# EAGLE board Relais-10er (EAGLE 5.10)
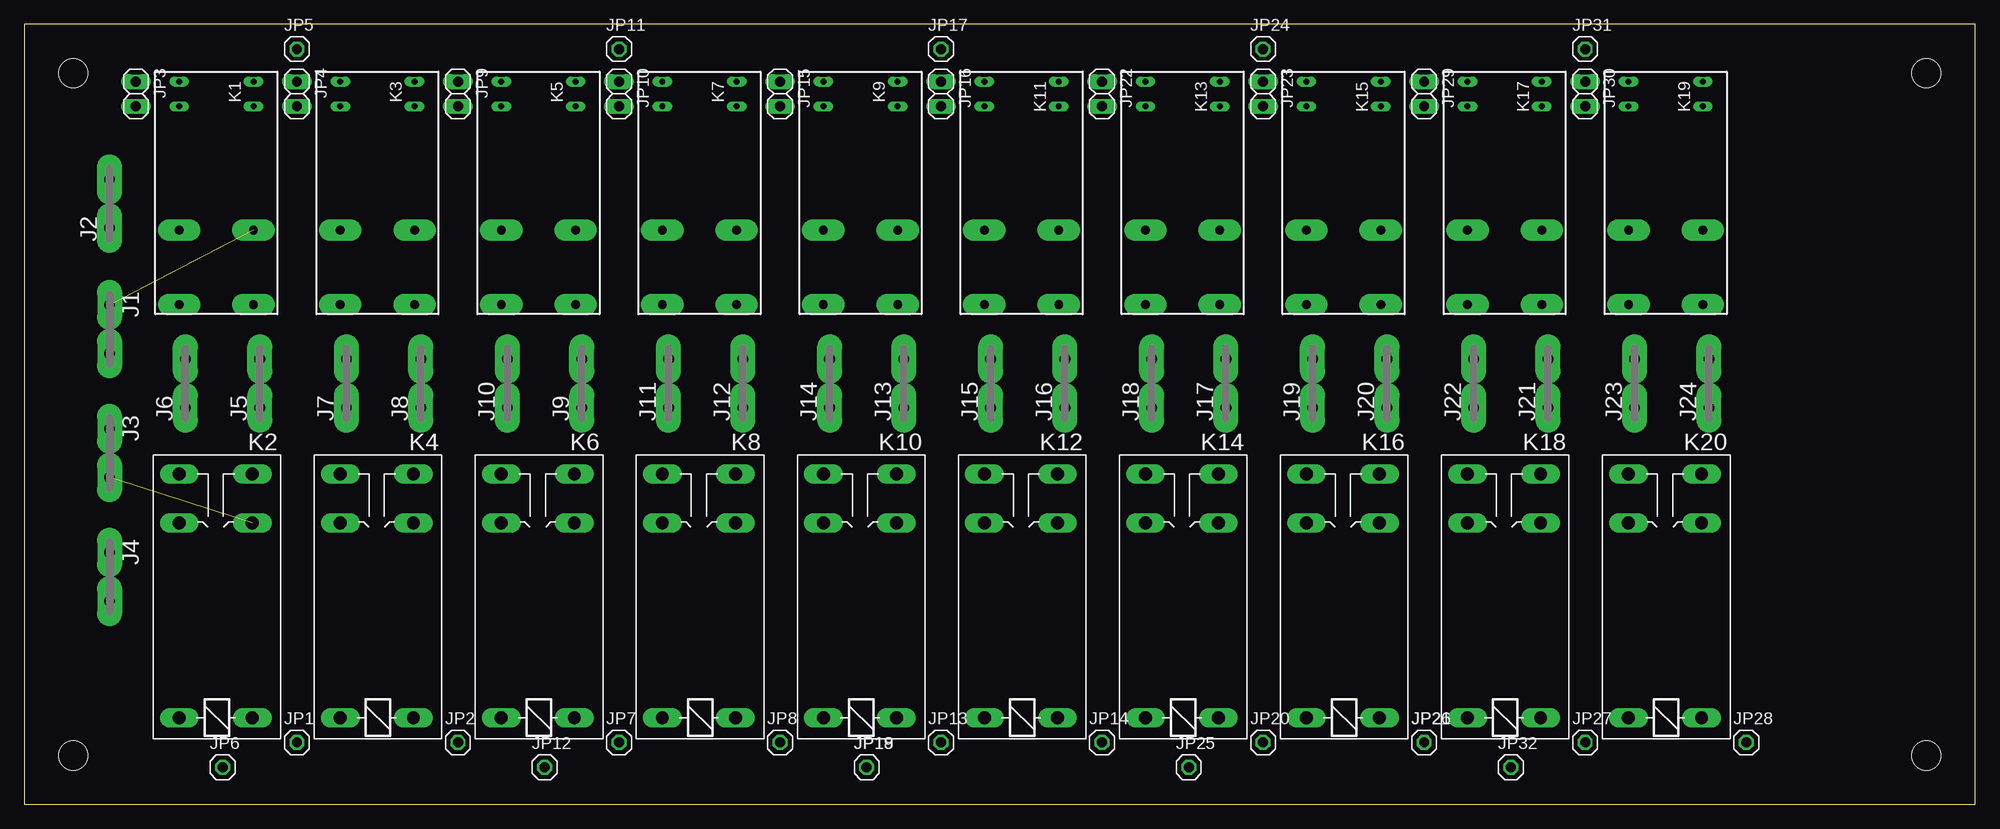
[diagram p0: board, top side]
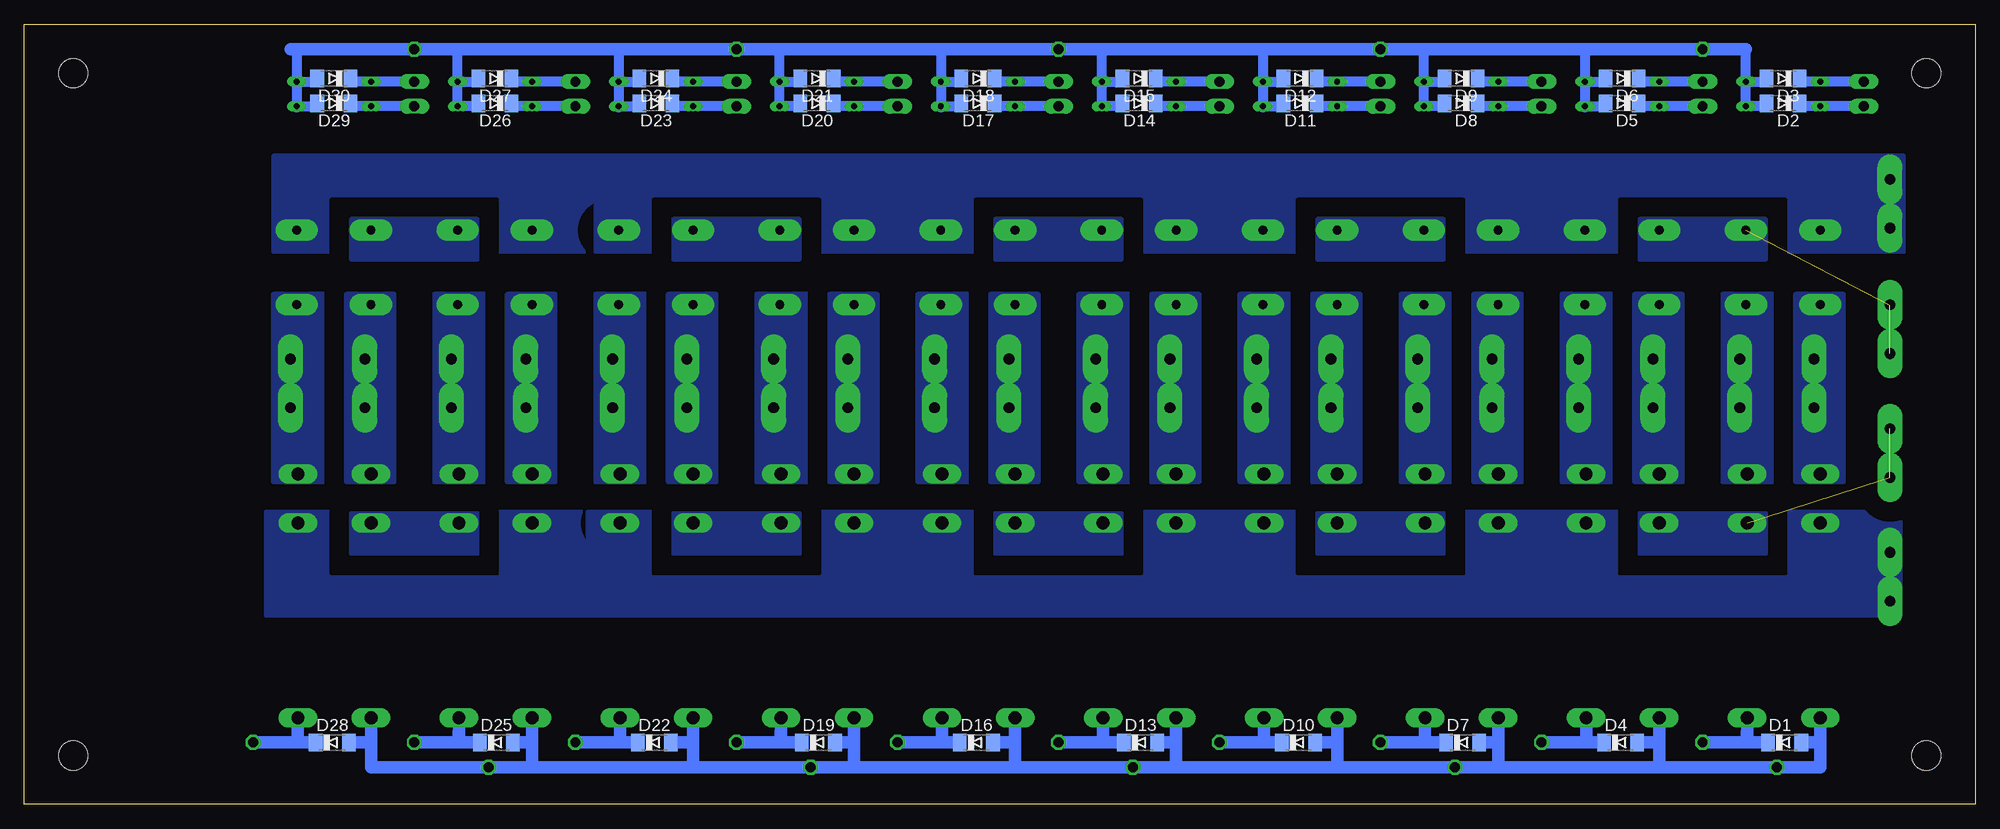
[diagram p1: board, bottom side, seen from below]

Size 200 x 80 mm. Coordinates in mm from the lower left corner, seen from the top.
Outline: 0,0 200,0 200,80 0,80 0,0
Copper layers (1+2*15+16): Top 0.035mm / dielectric 0.36mm / layer 2 0.018mm / dielectric 0.71mm / layer 15 0.018mm / dielectric 0.36mm / Bottom 0.035mm
Design rules "q-print.info": minimum track width 6mil, minimum drill 0.3mm, track to track 6mil, track to pad 6mil, pad to pad 6mil, via to via 6mil, smd to smd 6mil, copper to edge 8mil, drill to drill 10mil, minimum pad ring 8mil, minimum via ring 8mil, stop-mask expansion 4mil, vias tented up to drill 16mil, thermal gap 10mil
Net classes: 1 mains: width 4 mm, clearance 2 mm
Holes 3 mm at 5,75 5,5 195,5 195,75

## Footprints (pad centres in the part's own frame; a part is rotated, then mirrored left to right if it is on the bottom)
MINIMELF = smd 1.4 x 1.8: A 1.7,0; C -1.7,0
F061.080 = drill 1.1 pad 2.54 long: 1A -2.5,0; 1B 2.5,0
1X01 = drill 1.016 octagon: 1 0,0
1X02 = drill 1.016 long: 1 -1.27,0; 2 1.27,0
DE2A-L2 = drill 0.61 long: 1 -8.89,-3.81; 2 -6.35,-3.81; 7 -6.35,3.81; 8 -8.89,3.81 | drill 0.9 pad 2.184 long: 3 6.35,-3.81; 4 13.97,-3.81; 5 13.97,3.81; 6 6.35,3.81
G2R2A = drill 1.321 long: 1 -2.54,-3.683; 2 -2.54,3.81; P1 17.45,3.81; P2 17.45,-3.683; S1 22.454,3.81; S2 22.454,-3.683

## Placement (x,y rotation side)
D1  1N4148DO35-7  [MINIMELF]  19.53,6.35 0 bottom
D2  1N4148DO35-7  [MINIMELF]  19.68,71.91 180 bottom
D3  1N4148DO35-7  [MINIMELF]  19.68,74.45 180 bottom
D4  1N4148DO35-7  [MINIMELF]  36.35,6.35 0 bottom
D5  1N4148DO35-7  [MINIMELF]  36.19,71.91 180 bottom
D6  1N4148DO35-7  [MINIMELF]  36.2,74.45 180 bottom
D7  1N4148DO35-7  [MINIMELF]  52.55,6.35 0 bottom
D8  1N4148DO35-7  [MINIMELF]  52.7,71.91 180 bottom
D9  1N4148DO35-7  [MINIMELF]  52.7,74.45 180 bottom
D10  1N4148DO35-7  [MINIMELF]  69.37,6.35 0 bottom
D11  1N4148DO35-7  [MINIMELF]  69.21,71.91 180 bottom
D12  1N4148DO35-7  [MINIMELF]  69.22,74.45 180 bottom
D13  1N4148DO35-7  [MINIMELF]  85.57,6.35 0 bottom
D14  1N4148DO35-7  [MINIMELF]  85.72,71.91 180 bottom
D15  1N4148DO35-7  [MINIMELF]  85.72,74.45 180 bottom
D16  1N4148DO35-7  [MINIMELF]  102.39,6.35 0 bottom
D17  1N4148DO35-7  [MINIMELF]  102.23,71.91 180 bottom
D18  1N4148DO35-7  [MINIMELF]  102.23,74.45 180 bottom
D19  1N4148DO35-7  [MINIMELF]  118.59,6.35 0 bottom
D20  1N4148DO35-7  [MINIMELF]  118.75,71.91 180 bottom
D21  1N4148DO35-7  [MINIMELF]  118.74,74.45 180 bottom
D22  1N4148DO35-7  [MINIMELF]  135.41,6.35 0 bottom
D23  1N4148DO35-7  [MINIMELF]  135.25,71.91 180 bottom
D24  1N4148DO35-7  [MINIMELF]  135.25,74.45 180 bottom
D25  1N4148DO35-7  [MINIMELF]  151.61,6.35 0 bottom
D26  1N4148DO35-7  [MINIMELF]  151.76,71.91 180 bottom
D27  1N4148DO35-7  [MINIMELF]  151.76,74.45 180 bottom
D28  1N4148DO35-7  [MINIMELF]  168.43,6.35 0 bottom
D29  1N4148DO35-7  [MINIMELF]  168.27,71.91 180 bottom
D30  1N4148DO35-7  [MINIMELF]  168.28,74.45 180 bottom
J1  Netz-X1  [F061.080]  8.73,48.74 270 top
J2  Netz-X2  [F061.080]  8.73,61.59 90 top
J3  Schalter-X1  [F061.080]  8.73,36.04 270 top
J4  Schalter-X2  [F061.080]  8.73,23.34 270 top
J5  A1-X1  [F061.080]  24.13,43.18 90 top
J6  A1-X2  [F061.080]  16.51,43.18 90 top
J7  A2-X1  [F061.080]  33.02,43.18 90 top
J8  A2-X2  [F061.080]  40.64,43.18 90 top
J9  A1-X1  [F061.080]  57.15,43.18 90 top
J10  A1-X2  [F061.080]  49.53,43.18 90 top
J11  A2-X1  [F061.080]  66.04,43.18 90 top
J12  A2-X2  [F061.080]  73.66,43.18 90 top
J13  A1-X1  [F061.080]  90.17,43.18 90 top
J14  A1-X2  [F061.080]  82.55,43.18 90 top
J15  A2-X1  [F061.080]  99.06,43.18 90 top
J16  A2-X2  [F061.080]  106.68,43.18 90 top
J17  A1-X1  [F061.080]  123.19,43.18 90 top
J18  A1-X2  [F061.080]  115.57,43.18 90 top
J19  A2-X1  [F061.080]  132.08,43.18 90 top
J20  A2-X2  [F061.080]  139.7,43.18 90 top
J21  A1-X1  [F061.080]  156.21,43.18 90 top
J22  A1-X2  [F061.080]  148.59,43.18 90 top
J23  A2-X1  [F061.080]  165.1,43.18 90 top
J24  A2-X2  [F061.080]  172.72,43.18 90 top
JP1  [1X01]  27.94,6.35 0 top
JP2  [1X01]  44.45,6.35 0 top
JP3  [1X02]  11.43,72.87 270 top
JP4  [1X02]  27.94,72.87 270 top
JP5  [1X01]  27.94,77.47 0 top
JP6  [1X01]  20.32,3.81 0 top
JP7  [1X01]  60.96,6.35 0 top
JP8  [1X01]  77.47,6.35 0 top
JP9  [1X02]  44.45,72.87 270 top
JP10  [1X02]  60.96,72.87 270 top
JP11  [1X01]  60.96,77.47 0 top
JP12  [1X01]  53.34,3.81 0 top
JP13  [1X01]  93.98,6.35 0 top
JP14  [1X01]  110.49,6.35 0 top
JP15  [1X02]  77.47,72.87 270 top
JP16  [1X02]  93.98,72.87 270 top
JP17  [1X01]  93.98,77.47 0 top
JP18  [1X01]  86.36,3.81 0 top
JP19  [1X01]  86.36,3.81 0 top
JP20  [1X01]  127,6.35 0 top
JP21  [1X01]  143.51,6.35 0 top
JP22  [1X02]  110.49,72.87 270 top
JP23  [1X02]  127,72.87 270 top
JP24  [1X01]  127,77.47 0 top
JP25  [1X01]  119.38,3.81 0 top
JP26  [1X01]  143.51,6.35 0 top
JP27  [1X01]  160.02,6.35 0 top
JP28  [1X01]  176.53,6.35 0 top
JP29  [1X02]  143.51,72.87 270 top
JP30  [1X02]  160.02,72.87 270 top
JP31  [1X01]  160.02,77.47 0 top
JP32  [1X01]  152.4,3.81 0 top
K1  DE2A-L2  [DE2A-L2]  19.68,65.25 270 top
K2  G2R2A  [G2R2A]  19.68,11.43 90 top
K3  DE2A-L2  [DE2A-L2]  36.2,65.25 270 top
K4  G2R2A  [G2R2A]  36.2,11.43 90 top
K5  DE2A-L2  [DE2A-L2]  52.7,65.25 270 top
K6  G2R2A  [G2R2A]  52.7,11.43 90 top
K7  DE2A-L2  [DE2A-L2]  69.22,65.25 270 top
K8  G2R2A  [G2R2A]  69.22,11.43 90 top
K9  DE2A-L2  [DE2A-L2]  85.72,65.25 270 top
K10  G2R2A  [G2R2A]  85.72,11.43 90 top
K11  DE2A-L2  [DE2A-L2]  102.23,65.25 270 top
K12  G2R2A  [G2R2A]  102.23,11.43 90 top
K13  DE2A-L2  [DE2A-L2]  118.75,65.25 270 top
K14  G2R2A  [G2R2A]  118.75,11.43 90 top
K15  DE2A-L2  [DE2A-L2]  135.25,65.25 270 top
K16  G2R2A  [G2R2A]  135.25,11.43 90 top
K17  DE2A-L2  [DE2A-L2]  151.76,65.25 270 top
K18  G2R2A  [G2R2A]  151.76,11.43 90 top
K19  DE2A-L2  [DE2A-L2]  168.28,65.25 270 top
K20  G2R2A  [G2R2A]  168.28,11.43 90 top

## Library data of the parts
D1-D30 = diode
J1-J24 = con-faston
JP1-JP32 = pinhead
K1 K3 K5 K7 K9 K11 K13 K15 K17 K19 = 11my-mechanics
K2 K4 K6 K8 K10 K12 K14 K16 K18 K20 = relay

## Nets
N$1 [mains]: J1.1A J1.1B K1.6 K3.3
N$2 [mains]: J2.1A J2.1B K1.3 K3.6
N$3 [mains]: J5.1A J5.1B K1.5 K2.S2
N$4 [mains]: J6.1A J6.1B K1.4 K2.S1
N$5 [mains]: J4.1A J4.1B K2.P1 K4.P2
N$6 [mains]: J3.1A J3.1B K2.P2 K4.P1
N$7: D2.A D3.A D5.A D6.A JP5.1 K1.7 K1.8 K3.7 K3.8
N$8: D3.C JP3.1 K1.1
N$9: D2.C JP3.2 K1.2
N$10 [mains]: K5.6 K7.3
N$11: D1.C JP1.1 K2.1
N$12 [mains]: K5.3 K7.6
N$13: D1.A D4.A JP6.1 K2.2 K4.2
N$14 [mains]: J7.1A J7.1B K3.4 K4.S1
N$15 [mains]: J8.1A J8.1B K3.5 K4.S2
N$16 [mains]: J9.1A J9.1B K5.5 K6.S2
N$17 [mains]: J10.1A J10.1B K5.4 K6.S1
N$18 [mains]: K6.P1 K8.P2
N$19: D6.C JP4.1 K3.1
N$20: D5.C JP4.2 K3.2
N$21 [mains]: K6.P2 K8.P1
N$22: D4.C JP2.1 K4.1
N$23: D8.A D9.A D11.A D12.A JP11.1 K5.7 K5.8 K7.7 K7.8
N$24: D9.C JP9.1 K5.1
N$25: D8.C JP9.2 K5.2
N$26: D7.C JP7.1 K6.1
N$27 [mains]: J11.1A J11.1B K7.4 K8.S1
N$28 [mains]: J12.1A J12.1B K7.5 K8.S2
N$29: D12.C JP10.1 K7.1
N$30: D11.C JP10.2 K7.2
N$31: D10.C JP8.1 K8.1
N$32: D7.A D10.A JP12.1 K6.2 K8.2
N$33 [mains]: K9.6 K11.3
N$35 [mains]: K9.3 K11.6
N$36 [mains]: J13.1A J13.1B K9.5 K10.S2
N$38 [mains]: J14.1A J14.1B K9.4 K10.S1
N$39 [mains]: K10.P1 K12.P2
N$40 [mains]: K10.P2 K12.P1
N$41: D14.A D15.A D17.A D18.A JP17.1 K9.7 K9.8 K11.7 K11.8
N$42: D15.C JP15.1 K9.1
N$43: D14.C JP15.2 K9.2
N$44: D13.C JP13.1 K10.1
N$45 [mains]: J15.1A J15.1B K11.4 K12.S1
N$46 [mains]: J16.1A J16.1B K11.5 K12.S2
N$47: D18.C JP16.1 K11.1
N$48: D17.C JP16.2 K11.2
N$49: D16.C JP14.1 K12.1
N$50: D13.A D16.A JP19.1 K10.2 K12.2
N$51 [mains]: K13.6 K15.3
N$52 [mains]: K13.3 K15.6
N$53 [mains]: J17.1A J17.1B K13.5 K14.S2
N$54 [mains]: J18.1A J18.1B K13.4 K14.S1
N$55 [mains]: K14.P1 K16.P2
N$56 [mains]: K14.P2 K16.P1
N$57: D20.A D21.A D23.A D24.A JP24.1 K13.7 K13.8 K15.7 K15.8
N$58: D21.C JP22.1 K13.1
N$59: D20.C JP22.2 K13.2
N$60: D19.C JP20.1 K14.1
N$61 [mains]: J19.1A J19.1B K15.4 K16.S1
N$62 [mains]: J20.1A J20.1B K15.5 K16.S2
N$63: D24.C JP23.1 K15.1
N$64: D23.C JP23.2 K15.2
N$65: D22.C JP21.1 K16.1
N$66: D19.A D22.A JP25.1 K14.2 K16.2
N$70: JP26.1
N$72 [mains]: K17.6 K19.3
N$73 [mains]: K17.3 K19.6
N$74 [mains]: J21.1A J21.1B K17.5 K18.S2
N$75 [mains]: J22.1A J22.1B K17.4 K18.S1
N$76 [mains]: K18.P1 K20.P2
N$77 [mains]: K18.P2 K20.P1
N$78: D26.A D27.A D29.A D30.A JP31.1 K17.7 K17.8 K19.7 K19.8
N$79: D27.C JP29.1 K17.1
N$80: D26.C JP29.2 K17.2
N$81: D25.C JP27.1 K18.1
N$82 [mains]: J23.1A J23.1B K19.4 K20.S1
N$83 [mains]: J24.1A J24.1B K19.5 K20.S2
N$84: D30.C JP30.1 K19.1
N$85: D29.C JP30.2 K19.2
N$86: D28.C K20.1
N$87: D25.A D28.A JP32.1 K18.2 K20.2

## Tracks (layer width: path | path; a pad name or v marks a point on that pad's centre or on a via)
N$1  (2 unrouted)
  pour Bottom (no thermals): 21.43,60.01 34.45,60.01 34.45,55.88 21.43,55.88
N$2
  pour Bottom (isolate 2, rank 3, no thermals): 53.82,66.52 53.82,56.67 7.3,56.67 7.3,66.52
N$3
  pour Bottom (isolate 2, rank 4, no thermals): 19.68,33.02 25.88,33.02 25.88,52.39 19.68,52.39
N$4
  pour Bottom (isolate 2, no thermals): 13.49,52.39 13.49,33.02 18.41,33.02 18.42,52.39
N$5
  pour Bottom (isolate 2, rank 2, no thermals): 7.62,19.37 7.62,30 53.34,30 53.34,19.37
N$6  (2 unrouted)
  pour Bottom (no thermals): 21.43,29.84 34.45,29.84 34.45,25.72 21.43,25.72
N$7
  Bottom 1.016: K1.8 21.39,74.14 D3.A | D2.A 21.39,71.6 K1.7 K1.8 | K3.8 37.9,74.14 D6.A | K1.8 23.5,77.47 | K3.8 K3.7 37.9,71.6 D5.A | K3.8 40.01,77.47 40.64,77.47
  Bottom 1.27: 23.5,77.47 JP5.1 40.64,77.47 59.69,77.47 | K3.7
N$8
  Bottom 1.016: D3.C 17.98,74.14 K1.1 JP3.1
N$9
  Bottom 1.016: D2.C 17.98,71.6 K1.2 JP3.2
N$10
  pour Bottom (no thermals): 54.45,60.01 67.47,60.01 67.47,55.88 54.45,55.88
N$11
  Bottom 1.27: JP1.1 23.4,6.35 23.37,8.92 K2.1 23.37,6.35 D1.C
N$12
  pour Bottom (isolate 2, rank 3, no thermals): 84.3,66.52 84.3,56.67 40.32,56.67 40.32,66.52
N$13
  Bottom 1.27: 32.38,3.81 JP6.1 15.88,3.81 K2.2 15.88,6.35 D1.A | 32.38,3.81 32.38,6.35 | 32.38,6.35 K4.2 | 32.38,3.81 53.34,3.81 | 32.38,6.35 D4.A
N$14
  pour Bottom (isolate 2, no thermals): 34.92,52.39 30,52.39 30,33.02 34.92,33.02
N$15
  pour Bottom (isolate 2, rank 4, no thermals): 36.2,33.02 42.39,33.02 42.39,52.39 36.2,52.39
N$16
  pour Bottom (isolate 2, rank 4, no thermals): 52.7,33.02 58.9,33.02 58.9,52.39 52.7,52.39
N$17
  pour Bottom (isolate 2, no thermals): 46.51,52.39 46.51,33.02 51.44,33.02 51.44,52.39
N$18
  pour Bottom (isolate 2, rank 2, no thermals): 40.64,19.37 40.64,30 85.09,30 85.09,19.37
N$19
  Bottom 1.016: D6.C 34.49,74.14 K3.1 JP4.1
N$20
  Bottom 1.016: D5.C 34.49,71.6 K3.2 JP4.2
N$21
  pour Bottom (no thermals): 54.45,29.84 67.47,29.84 67.47,25.72 54.45,25.72
N$22
  Bottom 1.27: D4.C 39.88,6.35 | 39.88,6.35 K4.1 | 39.88,6.35 JP2.1
N$23
  Bottom 1.016: K5.8 54.41,74.14 D9.A | D8.A 54.41,71.6 K5.7 K5.8 | K7.8 70.92,74.14 D12.A | K5.8 56.52,77.47 | K7.8 K7.7 70.92,71.6 D11.A | K7.8 73.03,77.47 73.66,77.47
  Bottom 1.27: 56.52,77.47 JP11.1 73.66,77.47 90.17,77.47 | K7.7
N$24
  Bottom 1.016: D9.C 51.01,74.14 K5.1 JP9.1
N$25
  Bottom 1.016: D8.C 51.01,71.6 K5.2 JP9.2
N$26
  Bottom 1.27: JP7.1 56.42,6.35 56.39,8.92 K6.1 56.39,6.35 D7.C
N$27
  pour Bottom (isolate 2, no thermals): 67.94,52.39 63.02,52.39 63.02,33.02 67.94,33.02
N$28
  pour Bottom (isolate 2, rank 4, no thermals): 69.22,33.02 75.41,33.02 75.41,52.39 69.22,52.39
N$29
  Bottom 1.016: D12.C 67.52,74.14 K7.1 JP10.1
N$30
  Bottom 1.016: D11.C 67.52,71.6 K7.2 JP10.2
N$31
  Bottom 1.27: D10.C 72.9,6.35 | 72.9,6.35 K8.1 | 72.9,6.35 JP8.1
N$32
  Bottom 1.27: 65.41,3.81 JP12.1 48.9,3.81 K6.2 48.9,6.35 D7.A | 65.41,3.81 65.41,6.35 | 65.41,6.35 K8.2 | 65.41,3.81 86.36,3.81 | 65.41,6.35 D10.A
N$33
  pour Bottom (no thermals): 87.47,60.01 100.49,60.01 100.49,55.88 87.47,55.88
N$34
  pour Bottom (isolate 2, rank 3, no thermals): 84.3,66.52 84.3,56.67 73.34,56.67 73.34,66.52
N$35
  pour Bottom (isolate 2, rank 3, no thermals): 119.86,66.52 119.86,56.67 73.34,56.67 73.34,66.52
N$36
  pour Bottom (isolate 2, rank 4, no thermals): 85.72,33.02 91.92,33.02 91.92,52.39 85.72,52.39
N$37
  pour Bottom (isolate 2, rank 2, no thermals): 73.66,19.37 73.66,30 85.09,30 85.09,19.37
N$38
  pour Bottom (isolate 2, no thermals): 79.53,52.39 79.53,33.02 84.45,33.02 84.46,52.39
N$39
  pour Bottom (isolate 2, rank 2, no thermals): 73.66,19.37 73.66,30 119.38,30 119.38,19.37
N$40
  pour Bottom (no thermals): 87.47,29.84 100.49,29.84 100.49,25.72 87.47,25.72
N$41
  Bottom 1.016: K9.8 87.42,74.14 D15.A | D14.A 87.42,71.6 K9.7 K9.8 | K11.8 103.94,74.14 D18.A | K9.8 89.53,77.47 | K11.8 K11.7 103.94,71.6 D17.A | K11.8 106.05,77.47 106.68,77.47
  Bottom 1.27: 89.53,77.47 JP17.1 106.68,77.47 125.73,77.47 | K11.7
N$42
  Bottom 1.016: D15.C 84.03,74.14 K9.1 JP15.1
N$43
  Bottom 1.016: D14.C 84.03,71.6 K9.2 JP15.2
N$44
  Bottom 1.27: JP13.1 89.44,6.35 89.41,8.92 K10.1 89.41,6.35 D13.C
N$45
  pour Bottom (isolate 2, no thermals): 100.97,52.39 96.04,52.39 96.04,33.02 100.97,33.02
N$46
  pour Bottom (isolate 2, rank 4, no thermals): 102.23,33.02 108.43,33.02 108.43,52.39 102.23,52.39
N$47
  Bottom 1.016: D18.C 100.53,74.14 K11.1 JP16.1
N$48
  Bottom 1.016: D17.C 100.53,71.6 K11.2 JP16.2
N$49
  Bottom 1.27: D16.C 105.92,6.35 | 105.92,6.35 K12.1 | 105.92,6.35 JP14.1
N$50
  Bottom 1.27: 98.42,3.81 JP19.1 81.92,3.81 K10.2 81.92,6.35 D13.A | 98.42,3.81 98.42,6.35 | 98.42,6.35 K12.2 | 98.42,3.81 119.38,3.81 | 98.42,6.35 D16.A
N$51
  pour Bottom (no thermals): 120.49,60.01 133.51,60.01 133.51,55.88 120.49,55.88
N$52
  pour Bottom (isolate 2, rank 3, no thermals): 141.45,66.52 141.45,56.67 106.36,56.67 106.36,66.52
N$53
  pour Bottom (isolate 2, rank 4, no thermals): 118.75,33.02 124.94,33.02 124.94,52.39 118.75,52.39
N$54
  pour Bottom (isolate 2, no thermals): 112.55,52.39 112.55,33.02 117.47,33.02 117.48,52.39
N$55
  pour Bottom (isolate 2, rank 2, no thermals): 106.68,19.37 106.68,30 142.24,30 142.24,19.37
N$56
  pour Bottom (no thermals): 120.49,29.84 133.51,29.84 133.51,25.72 120.49,25.72
N$57
  Bottom 1.016: K13.8 120.44,74.14 D21.A | D20.A 120.44,71.6 K13.7 K13.8 | K15.8 136.96,74.14 D24.A | K13.8 122.56,77.47 | K15.8 K15.7 136.96,71.6 D23.A | K15.8 139.06,77.47 139.7,77.47
  Bottom 1.27: 122.56,77.47 JP24.1 139.7,77.47 | K15.7
N$58
  Bottom 1.016: D21.C 117.05,74.14 K13.1 JP22.1
N$59
  Bottom 1.016: D20.C 117.05,71.6 K13.2 JP22.2
N$60
  Bottom 1.27: JP20.1 122.46,6.35 122.43,8.92 K14.1 122.43,6.35 D19.C
N$61
  pour Bottom (isolate 2, no thermals): 133.99,52.39 129.06,52.39 129.06,33.02 133.99,33.02
N$62
  pour Bottom (isolate 2, rank 4, no thermals): 135.25,33.02 141.45,33.02 141.45,52.39 135.25,52.39
N$63
  Bottom 1.016: D24.C 133.56,74.14 K15.1 JP23.1
N$64
  Bottom 1.016: D23.C 133.56,71.6 K15.2 JP23.2
N$65
  Bottom 1.27: D22.C 138.94,6.35 | 138.94,6.35 K16.1 | 138.94,6.35 JP21.1
N$66
  Bottom 1.27: D19.A 114.94,6.35 K14.2 114.94,3.81 JP25.1 131.44,3.81 131.44,6.35 | 131.44,6.35 K16.2 | 131.44,6.35 D22.A
N$67
  pour Bottom (isolate 2, rank 3, no thermals): 152.88,66.52 152.88,56.67 106.36,56.67 106.36,66.52
N$68
  pour Bottom (isolate 2, rank 2, no thermals): 106.68,19.37 106.68,30 152.4,30 152.4,19.37
N$69
  Bottom 1.27: 139.7,77.47 158.75,77.47
N$70
  Bottom 1.27: 138.94,6.35 JP26.1
N$71
  Bottom 1.27: 131.44,3.81 152.4,3.81
N$72
  pour Bottom (no thermals): 153.51,60.01 166.53,60.01 166.53,55.88 153.51,55.88
N$73
  pour Bottom (isolate 2, rank 3, no thermals): 174.47,66.52 174.47,56.67 139.38,56.67 139.38,66.52
N$74
  pour Bottom (isolate 2, rank 4, no thermals): 151.76,33.02 157.96,33.02 157.96,52.39 151.76,52.39
N$75
  pour Bottom (isolate 2, no thermals): 145.57,52.39 145.57,33.02 150.5,33.02 150.5,52.39
N$76
  pour Bottom (isolate 2, rank 2, no thermals): 139.7,19.37 139.7,30 175.26,30 175.26,19.37
N$77
  pour Bottom (no thermals): 153.51,29.84 166.53,29.84 166.53,25.72 153.51,25.72
N$78
  Bottom 1.016: K17.8 153.47,74.14 D27.A | D26.A 153.47,71.6 K17.7 K17.8 | K19.8 169.97,74.14 D30.A | K17.8 155.57,77.47 | K19.8 K19.7 169.97,71.6 D29.A | K19.8 172.09,77.47 172.72,77.47
  Bottom 1.27: 155.57,77.47 JP31.1 172.72,77.47 | K19.7
N$79
  Bottom 1.016: D27.C 150.06,74.14 K17.1 JP29.1
N$80
  Bottom 1.016: D26.C 150.06,71.6 K17.2 JP29.2
N$81
  Bottom 1.27: JP27.1 155.48,6.35 155.45,8.92 K18.1 155.45,6.35 D25.C
N$82
  pour Bottom (isolate 2, no thermals): 167,52.39 162.08,52.39 162.08,33.02 167,33.02
N$83
  pour Bottom (isolate 2, rank 4, no thermals): 168.28,33.02 174.47,33.02 174.47,52.39 168.28,52.39
N$84
  Bottom 1.016: D30.C 166.57,74.14 K19.1 JP30.1
N$85
  Bottom 1.016: D29.C 166.57,71.6 K19.2 JP30.2
N$86
  Bottom 1.27: D28.C 171.96,6.35 | 171.96,6.35 K20.1 | 171.96,6.35 176.53,6.35
N$87
  Bottom 1.27: D25.A 147.96,6.35 K18.2 147.96,3.81 JP32.1 164.47,3.81 164.47,6.35 | 164.47,6.35 K20.2 | 164.47,6.35 D28.A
